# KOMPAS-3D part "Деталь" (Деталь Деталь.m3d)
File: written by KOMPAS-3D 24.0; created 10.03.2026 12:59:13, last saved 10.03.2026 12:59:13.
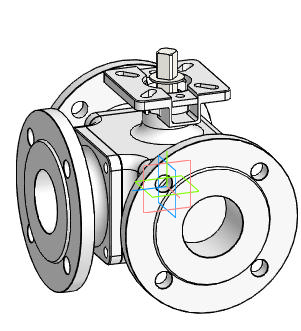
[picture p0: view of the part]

Document properties: Автор: R2D2; Полное имя файла: E:\Работа\Зайцев\BV3232P(4pc)-FP-3WL-F-ISO-H Кран шаровой DN.ru Ду15-100 Ру16\DN65\исходные материалы\Деталь Деталь.m3d

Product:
- Body: Твердое тело1  | qty 1
- Part/product: Деталь
    additional columns: Типовые

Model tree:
1. Твердое тело1  (labels: Твердое тело1)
